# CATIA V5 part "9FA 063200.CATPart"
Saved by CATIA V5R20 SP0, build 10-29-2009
Part number: 9FA 063200
Revision: ANY
Definition: UNKNOWN
Nomenclature: 9FA 063200
Source: Unknown
Bounding box of the stored display mesh (mm): x -3 to 3, y -9.95 to 10.05, z -3 to 3
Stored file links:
  C:\Users\Utente\Desktop\IO LAVORO\3D X SITO CF\CUMSA\3D files FA\FA 063200\9FA 063200.CATPart

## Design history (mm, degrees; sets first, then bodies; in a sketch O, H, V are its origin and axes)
Body1 "Redondeo2" (main body)
  Solid1: solid without history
